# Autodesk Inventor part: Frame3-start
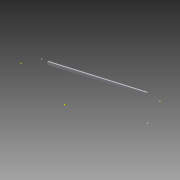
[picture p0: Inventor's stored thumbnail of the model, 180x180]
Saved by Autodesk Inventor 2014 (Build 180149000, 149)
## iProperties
Created: 2009-05
Part Number: Frame3-start
Document SubType Name: Modeling
Designer: millerpa
Density: 1 g/cm^3
Material: Generic
Appearance: Default
Author: millerpa
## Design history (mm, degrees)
derived "Skeleton-frame-start.ipt"
  sketch "Sketch4"
    geometry: L1 (-19.05, -44.45)-(19.05, -44.45) reference; L2 (19.05, -44.45)-(19.05, 44.45) reference; L3 (19.05, 44.45)-(-19.05, 44.45) reference; L4 (-19.05, 44.45)-(-19.05, -44.45) reference; 4 further points
  workplane "Work Plane1"
  workplane "Work Plane2"
  workplane "Work Plane3"
  workplane "Work Plane4"
  workplane "Work Plane5"
  workplane "Work Plane6"
extrude "Extrusion1" new body sketch "Sketch4" stored distance "d4" = 10; taper "d6" = 0 deg
body "Solid1"
feature "Srf2::Skeleton-frame-start.ipt"
body "Srf1"
feature "Srf3::Skeleton-frame-start.ipt"
body "Srf2"
other parameters: "d52" = 45 deg, "d53" = 45 deg, "d0_1" = 3772.27615, "d1" = 914.4, "d2" = 1662.8558, "d26" = 38.1, "d27" = 88.9, "d28" = 19.05, "d29" = 44.45, "d30" = 76.2, "d31" = 127, "d32" = 38.1, "d33" = 88.9, "d34" = 19.05, "d35" = 44.45, "d36" = 76.2, "d37" = 127, "d38" = 38.1, "d39" = 88.9, "d40" = 19.05, "d41" = 44.45, "d42" = 76.2, "d43" = 127, "d44" = 38.1, "d45" = 88.9, "d46" = 19.05, "d47" = 44.45, "d48" = 76.2, "d49" = 127, "d3" = 14.25776, "d5" = 14.25776, "d7" = 14.25776, "d8" = 14.25776, "d9" = 304.8, "d10" = 304.8, "FrameW" = 38.1, "FrameH" = 88.9, "d12" = 38.1, "d13" = 88.9, "d14" = 19.05, "d15" = 44.45, "d16" = 38.1, "d17" = 88.9, "d18" = 19.05, "d19" = 44.45, "d20" = 76.2, "d21" = 127
